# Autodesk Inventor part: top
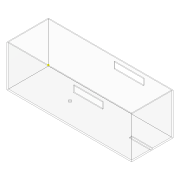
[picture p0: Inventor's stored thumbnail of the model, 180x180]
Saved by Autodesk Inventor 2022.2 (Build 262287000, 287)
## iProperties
Created: 2022-03
Part Number: top
Material: Polycarbonate, Clear
Document SubType Name: Modeling
Designer: OHIL G H
Density: 1.2 g/cm^3
Appearance: Polycarbonate - Clear
Author: OHIL G H
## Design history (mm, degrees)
sketch "Sketch1"
  geometry: L1 (0, 0)-(300, 0); L2 (300, 0)-(300, 100); L3 (300, 100)-(0, 100); L4 (0, 100)-(0, 0)
  constraints: 8 end point, 2 parallel, 1 horizontal, 1 perpendicular
  dimensions: "d0" = 300 distance of L3.end L2.end; "d1" = 100 distance of L2.end L1.end
extrude "Extrusion1" new body sketch "Sketch1" distance "d2" = 100; taper "d3" = 0 deg
sketch "Sketch2"
  geometry: L1 (2, -2)-(298, -2); L2 (298, -2)-(298, -98); L3 (298, -98)-(2, -98); L4 (2, -98)-(2, -2); L5 (300, 0)-(0, 0) reference; L6 (300, 0)-(300, -100) reference; L7 (300, -100)-(0, -100) reference; L8 (0, 0)-(0, -100) reference
  constraints: 8 end point, 2 parallel, 1 horizontal, 1 perpendicular
  dimensions: "d4" = 2 distance between parallel lines of L1 L5; "d5" = 2 distance between parallel lines of L6 L2; "d6" = 2 distance between parallel lines of L7 L3; "d7" = 2 distance between parallel lines of L8 L4
extrude "Extrusion2" cut sketch "Sketch2" distance "d8" = 98; taper "d9" = 0 deg
sketch "Sketch3"
  geometry: L1 (160, 90)-(230, 90); L2 (230, 90)-(230, 75); L3 (230, 75)-(160, 75); L4 (160, 75)-(160, 90); L5 (300, 100)-(0, 100) reference; L6 (300, 0)-(300, 100) reference; 2 further points
  constraints: 8 end point, 2 parallel, 1 horizontal, 1 midpoint, 1 perpendicular
  dimensions: "d10" = 70 distance of L2.end L3.end; "d11" = 15 distance of L1.end L2.end; "d12" = 10 distance between parallel lines of L5 L1; "d13" = 70 distance from line of L6 point (230, 82.5)
extrude "Extrusion3" cut sketch "Sketch3" extent not by distance; stored distance "d14" = 0; taper "d15" = 0 deg
sketch "Sketch4"
  geometry: L1 (0, 0)-(0, 100) reference; L2 (0, 100)-(300, 100) reference; C1 r 3.25 at (50, 50)
  constraints: 1 centre point
  dimensions: "d16" = 6.5 diameter of C1; "d17" = 50 distance from line of C1.centre L1; "d18" = 50 distance from line of L2 C1.centre
extrude "Extrusion4" cut sketch "Sketch4" distance "d19" = 10; taper "d20" = 0 deg
sketch "Sketch5"
  geometry: L1 (290, 54.47)-(250, 54.47); L2 (250, 54.47)-(250, 59.47); L3 (250, 59.47)-(290, 59.47); L4 (290, 59.47)-(290, 54.47); L5 (300, 0)-(300, 100) reference; 1 further point
  constraints: 8 end point, 2 parallel, 1 horizontal, 1 perpendicular
  dimensions: "d21" = 40 distance of L2.end L3.end; "d22" = 5 distance of L1.end L2.end; "d23" = 10 distance between parallel lines of L4 L5
extrude "Extrusion5" cut sketch "Sketch5" distance "d24" = 10; taper "d25" = 0 deg
sketch "Sketch6"
  geometry: L1 (250, -59.47)-(250, -54.47) reference; L2 (250, -59.47)-(290, -59.47) reference; L3 (250, -54.47)-(290, -54.47); L4 (290, -54.47)-(290, -59.47); L5 (290, -59.47)-(250, -59.47); L6 (250, -59.47)-(250, -54.47); 1 further point
  constraints: 8 end point, 2 parallel, 1 horizontal, 1 perpendicular
extrude "Extrusion6" join sketch "Sketch6" distance "d26" = 2; taper "d27" = 0 deg
sketch "Sketch7"
  geometry: 1 further point
sketch "Sketch8"
  geometry: L1 (298, -2)-(298, -98) reference; L2 (298, -47.25)-(248, -47.25); L3 (248, -47.25)-(248, -52.75); L4 (248, -52.75)-(298, -52.75); L5 (298, -52.75)-(298, -47.25); L6 (300, 0)-(0, 0) reference; 1 further point
  constraints: 8 end point, 2 parallel, 1 horizontal, 1 perpendicular, 1 point on line
  dimensions: "d28" = 50 distance of L4.end L3.end; "d29" = 5.5 distance of L3.end L2.end; "d30" = 47.25 distance between parallel lines of L6 L2
extrude "Extrusion7" cut sketch "Sketch8" extent not by distance; stored distance "d31" = 0; taper "d32" = 0 deg
sketch "Sketch9"
  geometry: C1 r 3.25 at (50, -50) reference; C2 r 3.25 at (50, -50); 1 further point
  constraints: 1 centre point, 1 coincident
extrude "Extrusion8" join sketch "Sketch9" distance "d33" = 2; taper "d34" = 0 deg
sketch "Sketch10"
  geometry: L1 (0, 0)-(0, -100) reference; L2 (300, 0)-(0, 0) reference; C1 r 3.25 at (100, -48)
  constraints: 1 centre point
  dimensions: "d35" = 6.5 diameter of C1; "d36" = 100 distance from line of C1.centre L1; "d37" = 48 distance from line of L2 C1.centre
extrude "Extrusion9" cut sketch "Sketch10" distance "d38" = 2; taper "d39" = 0 deg
body "Solid1"
